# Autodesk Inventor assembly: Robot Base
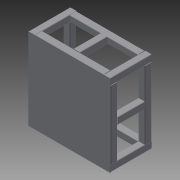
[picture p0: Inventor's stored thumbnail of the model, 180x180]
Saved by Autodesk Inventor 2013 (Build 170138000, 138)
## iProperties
Created: 2008-05
Part Number: Robot Base
Document SubType Name: Assembly
Designer: Jayson Martinez
Author: Jayson Martinez
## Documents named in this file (6)
- C:\Users\boganb\Documents\B2 Design\Goodyear\2013 Tutorial Files\Assembly Optimization using FEA\Robot Base.iam
- C:\Users\boganb\Documents\B2 Design\Goodyear\2013 Tutorial Files\Assembly Optimization using FEA\corner.ipt
- C:\Users\boganb\Documents\B2 Design\Goodyear\2013 Tutorial Files\Assembly Optimization using FEA\Horizontal.ipt
- C:\Users\boganb\Documents\B2 Design\Goodyear\2013 Tutorial Files\Assembly Optimization using FEA\base_plate.ipt
- C:\Users\boganb\Documents\B2 Design\Goodyear\2013 Tutorial Files\Assembly Optimization using FEA\side.ipt
- C:\Users\boganb\Documents\B2 Design\Goodyear\2013 Tutorial Files\Assembly Optimization using FEA\top.ipt
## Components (20 placed, 5 different names)
1. base_plate:1
2. corner:1
3. corner:2
4. corner:3
5. corner:4
6. Horizontal:1
7. Horizontal:2
8. Horizontal:3
9. Horizontal:4
10. Horizontal:5
11. Horizontal:6
12. Horizontal:7
13. Horizontal:8
14. Horizontal:9
15. side:1
16. side:2
17. side:3
18. side:4
19. top:1
20. top:2
## Named parameters: d0_d33 = 0, d1_d34 = 0, d10_d35 = 0, d11_d36 = 0, d17_d29 = 0, d18_d30 = 0, d23_d31 = 0, d24_d32 = 0, d28_d51 = 0, d29_d54 = 0, d34_d50 = 0, d39_d49 = 0, d43_d48 = 0, d46_d52 = 0, d51_d56 = 0, d52_d55 = 0
